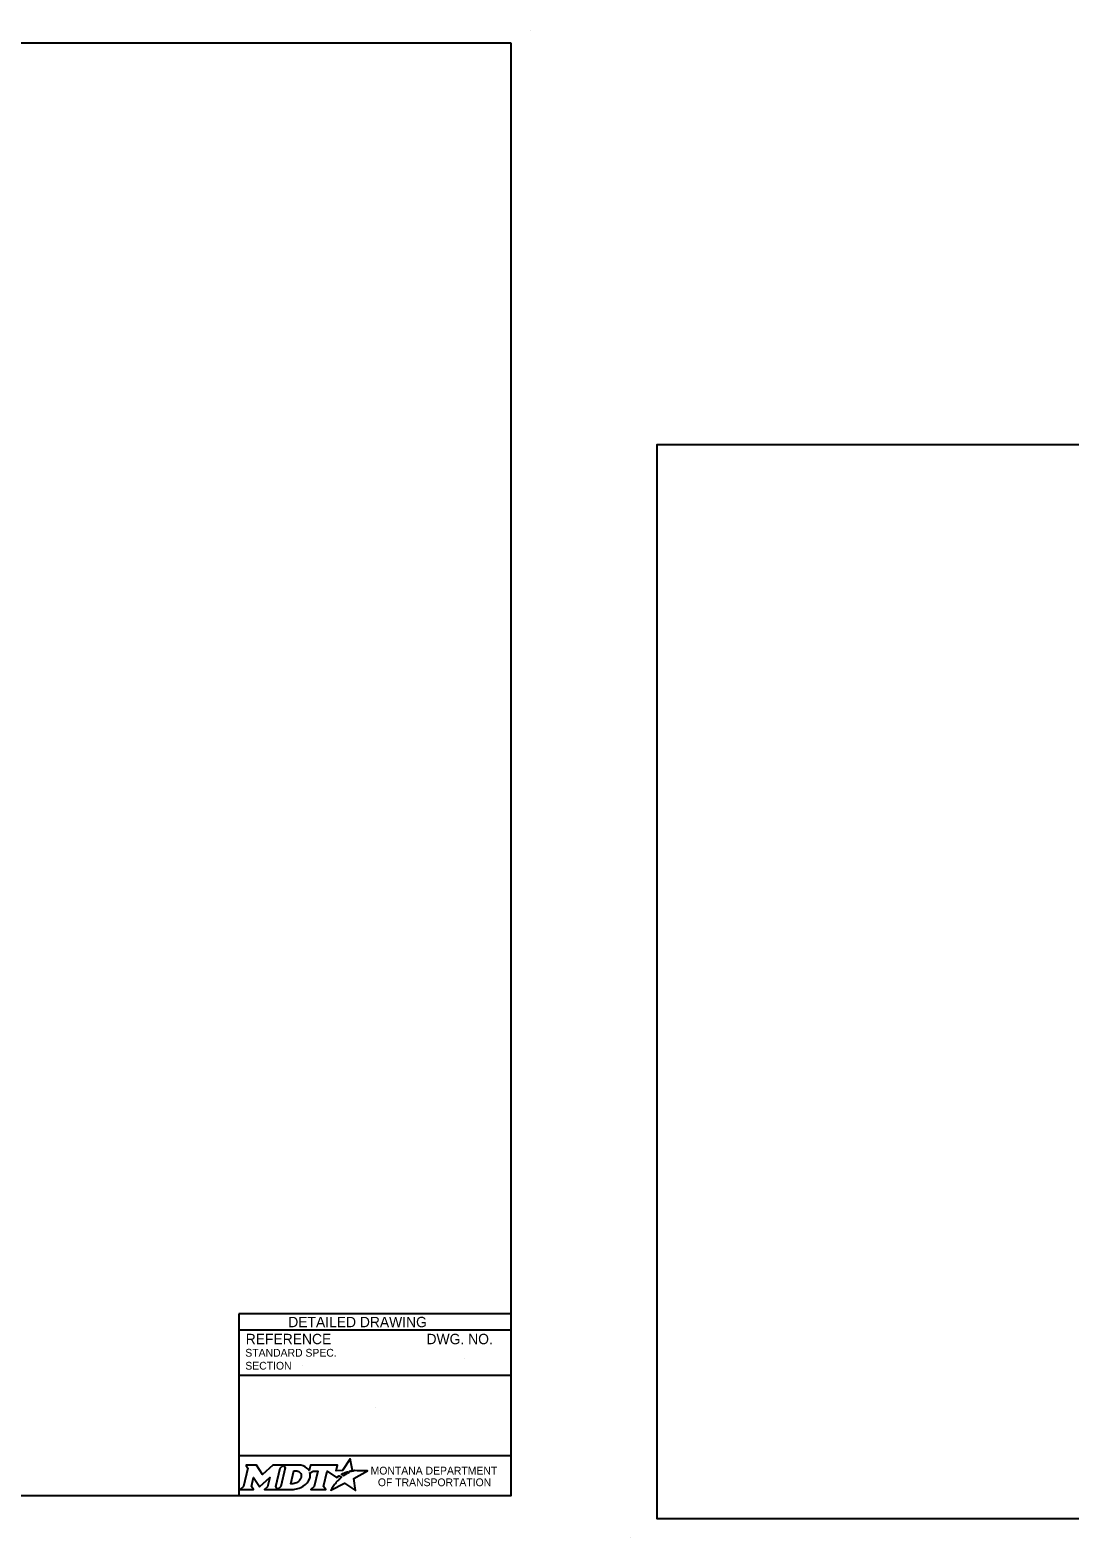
# Model space of a CAD drawing. Extents: x 49940 to 50043, y 49986 to 50011.
# Drawn here: x 50004.91 to 50012.92, y 49999.74 to 50011.36 of the extents above; entities that cross this region are included whole.
import ezdxf

# ---------------------------------------------------------------- set-up
doc = ezdxf.new("R2010")
doc.units = 0
doc.layers.add('Level 1', color=7, linetype='Continuous')
doc.layers.add('Level 2', color=7, linetype='Continuous')

msp = doc.modelspace()

# ---------------------------------------------------------------- linework, layer by layer
at = {"layer": 'Level 1'}
for p, q in [((50008.765, 50011.363), (50008.765, 50011.363)), ((50009.537, 49999.736), (50009.537, 49999.736))]:
    msp.add_line(p, q, dxfattribs=at)
for points in [[(50008.615, 50011.263), (50000.336, 50011.263), (50000.336, 50000.062), (50008.615, 50000.062)], [(50020.938, 50008.165), (50009.737, 50008.165), (50009.737, 49999.886), (50020.938, 49999.886)]]:
    msp.add_lwpolyline(points, close=True, dxfattribs=at)
at = {"layer": 'Level 2'}
for p, q in [((50008.615, 50001.462), (50006.515, 50001.462)), ((50006.515, 50001.462), (50006.515, 50000.062)), ((50008.615, 50001.337), (50006.515, 50001.337)), ((50007.009, 50001.063), (50007.009, 50001.063)), ((50008.251, 50001.122), (50008.251, 50001.122)), ((50008.615, 50000.987), (50006.515, 50000.987)), ((50007.565, 50000.738), (50007.565, 50000.738)), ((50008.615, 50000.369), (50006.515, 50000.369))]:
    msp.add_line(p, q, dxfattribs=at)
for points in [[(50007.377, 50000.245), (50007.367, 50000.25), (50007.378, 50000.253), (50007.39, 50000.255), (50007.373, 50000.345), (50007.313, 50000.254), (50007.266, 50000.253), (50007.276, 50000.297), (50007.067, 50000.297), (50007.057, 50000.255), (50007.051, 50000.263)], [(50006.57, 50000.297), (50006.584, 50000.274), (50006.551, 50000.131), (50006.525, 50000.108), (50006.627, 50000.108), (50006.613, 50000.131), (50006.629, 50000.201), (50006.673, 50000.132), (50006.678, 50000.132), (50006.753, 50000.202), (50006.737, 50000.13), (50006.712, 50000.108), (50006.814, 50000.108), (50006.8, 50000.132), (50006.833, 50000.274)], [(50006.833, 50000.274), (50006.859, 50000.297), (50006.776, 50000.297), (50006.697, 50000.224), (50006.652, 50000.297), (50006.57, 50000.297)], [(50006.972, 50000.297), (50006.859, 50000.297), (50006.873, 50000.275), (50006.839, 50000.131), (50006.814, 50000.108), (50006.925, 50000.108)], [(50006.996, 50000.211), (50006.995, 50000.203), (50006.992, 50000.193), (50006.988, 50000.185), (50006.982, 50000.178), (50006.976, 50000.171), (50006.968, 50000.164), (50006.959, 50000.16), (50006.95, 50000.156), (50006.941, 50000.154), (50006.932, 50000.153), (50006.916, 50000.153), (50006.94, 50000.253), (50006.956, 50000.253), (50006.963, 50000.252), (50006.971, 50000.25), (50006.977, 50000.247), (50006.983, 50000.243), (50006.988, 50000.238), (50006.992, 50000.232), (50006.995, 50000.226), (50006.996, 50000.218), (50006.996, 50000.215), (50006.996, 50000.211)], [(50007.064, 50000.238), (50007.088, 50000.251), (50007.125, 50000.251), (50007.097, 50000.131), (50007.069, 50000.108), (50007.185, 50000.108), (50007.168, 50000.131), (50007.196, 50000.251), (50007.268, 50000.2), (50007.289, 50000.215), (50007.309, 50000.204)], [(50007.253, 50000.148), (50007.237, 50000.124), (50007.233, 50000.116), (50007.227, 50000.107), (50007.225, 50000.103), (50007.33, 50000.156), (50007.414, 50000.101), (50007.401, 50000.194), (50007.508, 50000.252), (50007.458, 50000.253), (50007.428, 50000.253), (50007.407, 50000.254), (50007.401, 50000.252), (50007.396, 50000.251), (50007.387, 50000.249), (50007.377, 50000.245)], [(50007.327, 50000.217), (50007.324, 50000.215), (50007.306, 50000.225), (50007.316, 50000.231), (50007.32, 50000.233), (50007.329, 50000.237), (50007.335, 50000.239), (50007.343, 50000.243), (50007.35, 50000.245), (50007.362, 50000.238), (50007.358, 50000.236), (50007.353, 50000.233), (50007.349, 50000.231), (50007.344, 50000.228), (50007.342, 50000.227), (50007.339, 50000.225), (50007.337, 50000.224), (50007.334, 50000.222), (50007.332, 50000.221), (50007.329, 50000.219), (50007.327, 50000.217)], [(50006.97, 50000.116), (50006.979, 50000.118), (50006.992, 50000.124), (50007.012, 50000.135)], [(50007.267, 50000.164), (50007.267, 50000.164)]]:
    msp.add_lwpolyline(points, dxfattribs=at)
for centre, radius, start, end in [((50006.995, 50000.219), 0.0709, 339.5329, 15.8582), ((50006.951, 50000.236), 0.118, 300.9103, 339.1383)]:
    msp.add_arc(centre, radius, start, end, dxfattribs=at)
for centre, major_axis, ratio, start_param, end_param in [((50006.97, 50000.25), (0.0834, -0.0037), 0.568097, 0.61298, 1.570796), ((50007.026, 50000.257), (0.0361, -0.0295), 0.469099, 1.225588, 1.570796), ((50006.925, 50000.257), (0, 0.148), 0.987302, 3.139398, 3.456847), ((50007.26, 50000.156), (-0.00694, -0.00806), 0.008222, 0, 3.137361), ((50007.276, 50000.174), (-0.0098, -0.0102), 0.016458, 3.141593, 6.279097), ((50007.297, 50000.194), (-0.0112, -0.0097), 0.021651, 3.157348, 6.283185)]:
    msp.add_ellipse(centre, major_axis=major_axis, ratio=ratio, start_param=start_param, end_param=end_param, dxfattribs=at)

# ---------------------------------------------------------------- texts
for s, height, p in [('DETAILED DRAWING', 0.0799, (50006.896, 50001.36)), ('REFERENCE', 0.08, (50006.568, 50001.229)), ('DWG. NO.', 0.08, (50007.962, 50001.229)), ('STANDARD SPEC.', 0.06, (50006.565, 50001.133)), ('SECTION', 0.06, (50006.565, 50001.033)), ('MONTANA DEPARTMENT', 0.06, (50007.531, 50000.224)), ('OF TRANSPORTATION', 0.06, (50007.587, 50000.134))]:
    msp.add_text(s, height=height, dxfattribs=at).set_placement(p)

doc.saveas('drawing.dxf')
